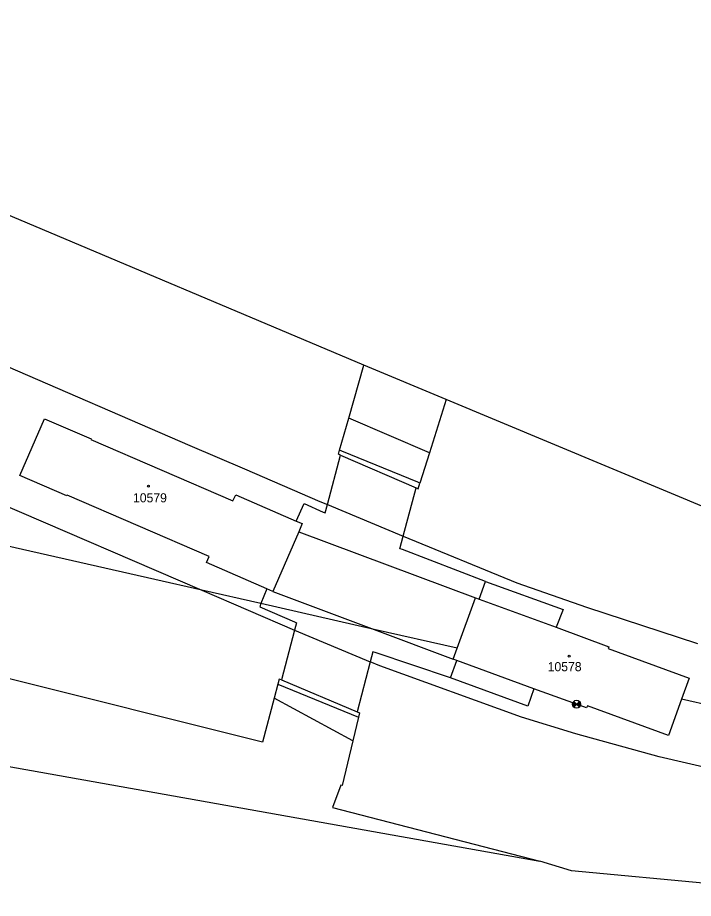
# Model space of a CAD drawing. Extents: x -825057 to -819383, y -1071633 to -1067888.
# Drawn here: x -823342.1 to -823216, y -1070428.6 to -1070264.3 of the extents above; entities that cross this region are included whole.
import ezdxf

# ---------------------------------------------------------------- set-up
doc = ezdxf.new("R2010")
doc.units = 0
for name, color, linetype in [('Vrstva 1', 7, 'Continuous'), ('Vrstva 19', 7, 'Continuous'), ('Vrstva 24', 7, 'Continuous'), ('Vrstva 25', 7, 'Continuous'), ('Vrstva 4', 7, 'Continuous')]:
    doc.layers.add(name, color=color, linetype=linetype)

msp = doc.modelspace()

# ---------------------------------------------------------------- linework, layer by layer
at = {"layer": 'Vrstva 1'}
for p, q in [((-823277.49, -1070329.14), (-823431.39, -1070264.33)), ((-823262.15, -1070335.56), (-823277.49, -1070329.14)), ((-823161.02, -1070377.79), (-823262.15, -1070335.56)), ((-823341.69, -1070349.75), (-823337.09, -1070339.14)), ((-823337.09, -1070339.14), (-823328.36, -1070342.91)), ((-823328.36, -1070342.91), (-823328.41, -1070343.05)), ((-823328.41, -1070343.05), (-823301.96, -1070354.47)), ((-823332.9, -1070353.55), (-823341.69, -1070349.75)), ((-823332.84, -1070353.42), (-823332.9, -1070353.55)), ((-823306.38, -1070364.84), (-823332.84, -1070353.42)), ((-823301.96, -1070354.47), (-823301.42, -1070353.33)), ((-823301.42, -1070353.33), (-823290.12, -1070358.24)), ((-823316.52, -1070369.14), (-823375.91, -1070355.64)), ((-823290.12, -1070358.24), (-823289, -1070358.72)), ((-823289, -1070358.72), (-823289.65, -1070360.23)), ((-823289.65, -1070360.23), (-823294.46, -1070371.37)), ((-823306.87, -1070365.98), (-823306.38, -1070364.84)), ((-823295.63, -1070370.87), (-823306.87, -1070365.98)), ((-823307.71, -1070371.15), (-823316.52, -1070369.14)), ((-823256, -1070372.82), (-823254.8, -1070369.54)), ((-823254.8, -1070369.54), (-823240.36, -1070374.76)), ((-823296.72, -1070373.64), (-823307.71, -1070371.15)), ((-823294.46, -1070371.37), (-823295.63, -1070370.87)), ((-823275.56, -1070378.45), (-823296.72, -1070373.64)), ((-823260.09, -1070381.97), (-823256.66, -1070372.58)), ((-823256.66, -1070372.58), (-823256, -1070372.82)), ((-823240.36, -1070374.76), (-823241.62, -1070378.01)), ((-823260.09, -1070381.97), (-823275.56, -1070378.45)), ((-823241.62, -1070378.01), (-823231.79, -1070381.68)), ((-823260.82, -1070383.98), (-823260.09, -1070381.97)), ((-823231.79, -1070381.68), (-823231.92, -1070382.04)), ((-823231.92, -1070382.04), (-823216.83, -1070387.54)), ((-823261.35, -1070387.47), (-823260.16, -1070384.22)), ((-823260.16, -1070384.22), (-823260.82, -1070383.98)), ((-823246.95, -1070392.79), (-823261.35, -1070387.47)), ((-823216.83, -1070387.54), (-823218.26, -1070391.49)), ((-823245.78, -1070389.52), (-823246.95, -1070392.79)), ((-823237.84, -1070392.4), (-823245.78, -1070389.52)), ((-823218.26, -1070391.49), (-823220.7, -1070398.24)), ((-823211.58, -1070393.01), (-823218.26, -1070391.49)), ((-823236, -1070393.07), (-823237.84, -1070392.4)), ((-823235.82, -1070392.72), (-823236, -1070393.07)), ((-823220.7, -1070398.24), (-823235.82, -1070392.72)), ((-823396.23, -1070394.68), (-823244.71, -1070421.69)), ((-823238.78, -1070423.45), (-823244.71, -1070421.69)), ((-823184.91, -1070428.62), (-823238.78, -1070423.45))]:
    msp.add_line(p, q, dxfattribs=at)
at = {"layer": 'Vrstva 24'}
for p, q in [((-823238.489, -1070392.025), (-823237.191, -1070392.775)), ((-823238.489, -1070392.775), (-823237.191, -1070392.025)), ((-823238.37, -1070392.93), (-823237.31, -1070391.87)), ((-823238.37, -1070391.87), (-823237.31, -1070392.93)), ((-823238.59, -1070392.4), (-823237.09, -1070392.4)), ((-823238.564, -1070392.206), (-823237.116, -1070392.594)), ((-823238.564, -1070392.594), (-823237.116, -1070392.206))]:
    msp.add_line(p, q, dxfattribs=at)
msp.add_circle((-823237.84, -1070392.4), 0.75, dxfattribs=at)
at = {"layer": 'Vrstva 25'}
for centre in [(-823317.71, -1070351.74), (-823239.21, -1070383.45)]:
    msp.add_circle(centre, 0.175, dxfattribs=at)
at = {"layer": 'Vrstva 4'}
for p, q in [((-823413.44, -1070299.44), (-823309.95, -1070344.12)), ((-823280.34, -1070339.05), (-823277.49, -1070329.14)), ((-823262.15, -1070335.56), (-823265.27, -1070345.52)), ((-823282.06, -1070345.04), (-823280.34, -1070339.05)), ((-823265.27, -1070345.52), (-823280.34, -1070339.05)), ((-823309.95, -1070344.12), (-823299.79, -1070348.5)), ((-823284.28, -1070355.15), (-823281.86, -1070345.96)), ((-823282.27, -1070345.78), (-823282.06, -1070345.04)), ((-823281.86, -1070345.96), (-823282.27, -1070345.78)), ((-823281.64, -1070345.21), (-823282.06, -1070345.04)), ((-823281.86, -1070345.96), (-823267.77, -1070352.03)), ((-823267.46, -1070351.01), (-823281.64, -1070345.21)), ((-823265.27, -1070345.52), (-823267.04, -1070351.18)), ((-823299.79, -1070348.5), (-823285.74, -1070354.58)), ((-823270.15, -1070361.03), (-823267.77, -1070352.03)), ((-823267.77, -1070352.03), (-823267.36, -1070352.2)), ((-823267.04, -1070351.18), (-823267.46, -1070351.01)), ((-823267.36, -1070352.2), (-823267.04, -1070351.18)), ((-823349.78, -1070353.02), (-823307.71, -1070371.15)), ((-823290.12, -1070358.24), (-823288.64, -1070354.96)), ((-823288.64, -1070354.96), (-823285.07, -1070356.57)), ((-823285.74, -1070354.58), (-823284.28, -1070355.15)), ((-823284.7, -1070356.73), (-823284.28, -1070355.15)), ((-823284.28, -1070355.15), (-823270.15, -1070361.03)), ((-823285.07, -1070356.57), (-823284.7, -1070356.73)), ((-823289.65, -1070360.23), (-823256.66, -1070372.58)), ((-823270.77, -1070363.4), (-823270.15, -1070361.03)), ((-823270.15, -1070361.03), (-823248.99, -1070369.77)), ((-823270.3, -1070363.57), (-823270.77, -1070363.4)), ((-823254.8, -1070369.54), (-823270.3, -1070363.57)), ((-823296.39, -1070399.5), (-823431.25, -1070365.81)), ((-823248.99, -1070369.77), (-823235.98, -1070374.33)), ((-823307.71, -1070371.15), (-823290.44, -1070378.59)), ((-823295.63, -1070370.87), (-823296.72, -1070373.64)), ((-823294.46, -1070371.37), (-823275.56, -1070378.45)), ((-823296.72, -1070373.64), (-823296.94, -1070374.21)), ((-823256, -1070372.82), (-823241.62, -1070378.01)), ((-823296.94, -1070374.21), (-823290.45, -1070377.06)), ((-823235.98, -1070374.33), (-823215.25, -1070381.08)), ((-823290.45, -1070377.06), (-823290.07, -1070377.2)), ((-823290.07, -1070377.2), (-823290.44, -1070378.59)), ((-823290.44, -1070378.59), (-823292.87, -1070387.87)), ((-823290.44, -1070378.59), (-823276.32, -1070384.5)), ((-823275.56, -1070378.45), (-823260.82, -1070383.98)), ((-823275.83, -1070382.61), (-823276.32, -1070384.5)), ((-823275.39, -1070382.78), (-823275.83, -1070382.61)), ((-823261.35, -1070387.47), (-823275.39, -1070382.78)), ((-823276.32, -1070384.5), (-823278.76, -1070393.81)), ((-823274.56, -1070385.23), (-823276.32, -1070384.5)), ((-823248.08, -1070394.84), (-823274.56, -1070385.23)), ((-823245.78, -1070389.52), (-823260.16, -1070384.22)), ((-823293.54, -1070388.66), (-823294.23, -1070391.28)), ((-823293.29, -1070387.7), (-823293.54, -1070388.66)), ((-823293.54, -1070388.66), (-823278.54, -1070394.83)), ((-823292.87, -1070387.87), (-823293.29, -1070387.7)), ((-823292.87, -1070387.87), (-823278.76, -1070393.81)), ((-823294.23, -1070391.28), (-823296.39, -1070399.5)), ((-823279.59, -1070399.23), (-823294.23, -1070391.28)), ((-823278.54, -1070394.83), (-823279.59, -1070399.23)), ((-823278.76, -1070393.81), (-823278.34, -1070393.98)), ((-823278.34, -1070393.98), (-823278.54, -1070394.83)), ((-823237.95, -1070397.92), (-823248.08, -1070394.84)), ((-823222.41, -1070402.19), (-823237.95, -1070397.92)), ((-823279.59, -1070399.23), (-823281.56, -1070407.54)), ((-823211.94, -1070404.65), (-823222.41, -1070402.19)), ((-823281.78, -1070407.49), (-823283.35, -1070411.64)), ((-823281.56, -1070407.54), (-823281.78, -1070407.49)), ((-823283.35, -1070411.64), (-823244.71, -1070421.69))]:
    msp.add_line(p, q, dxfattribs=at)

# ---------------------------------------------------------------- texts
at = {"layer": 'Vrstva 19'}
for s, p in [('10579', (-823320.573, -1070354.75)), ('10578', (-823243.22, -1070386.25))]:
    msp.add_text(s, height=1.7, dxfattribs=at).set_placement(p)

doc.saveas('drawing.dxf')
